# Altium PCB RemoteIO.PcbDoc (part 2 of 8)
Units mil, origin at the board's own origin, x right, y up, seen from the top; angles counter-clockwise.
Board outline 7874.02 x 2362.2 mil, 6 copper layers (Top Layer, GND1, Layer 2, PWR, GND2, Bottom Layer), stack 60.956 mil thick; 655 components, 447 nets, 2607 pads, 1444 vias.
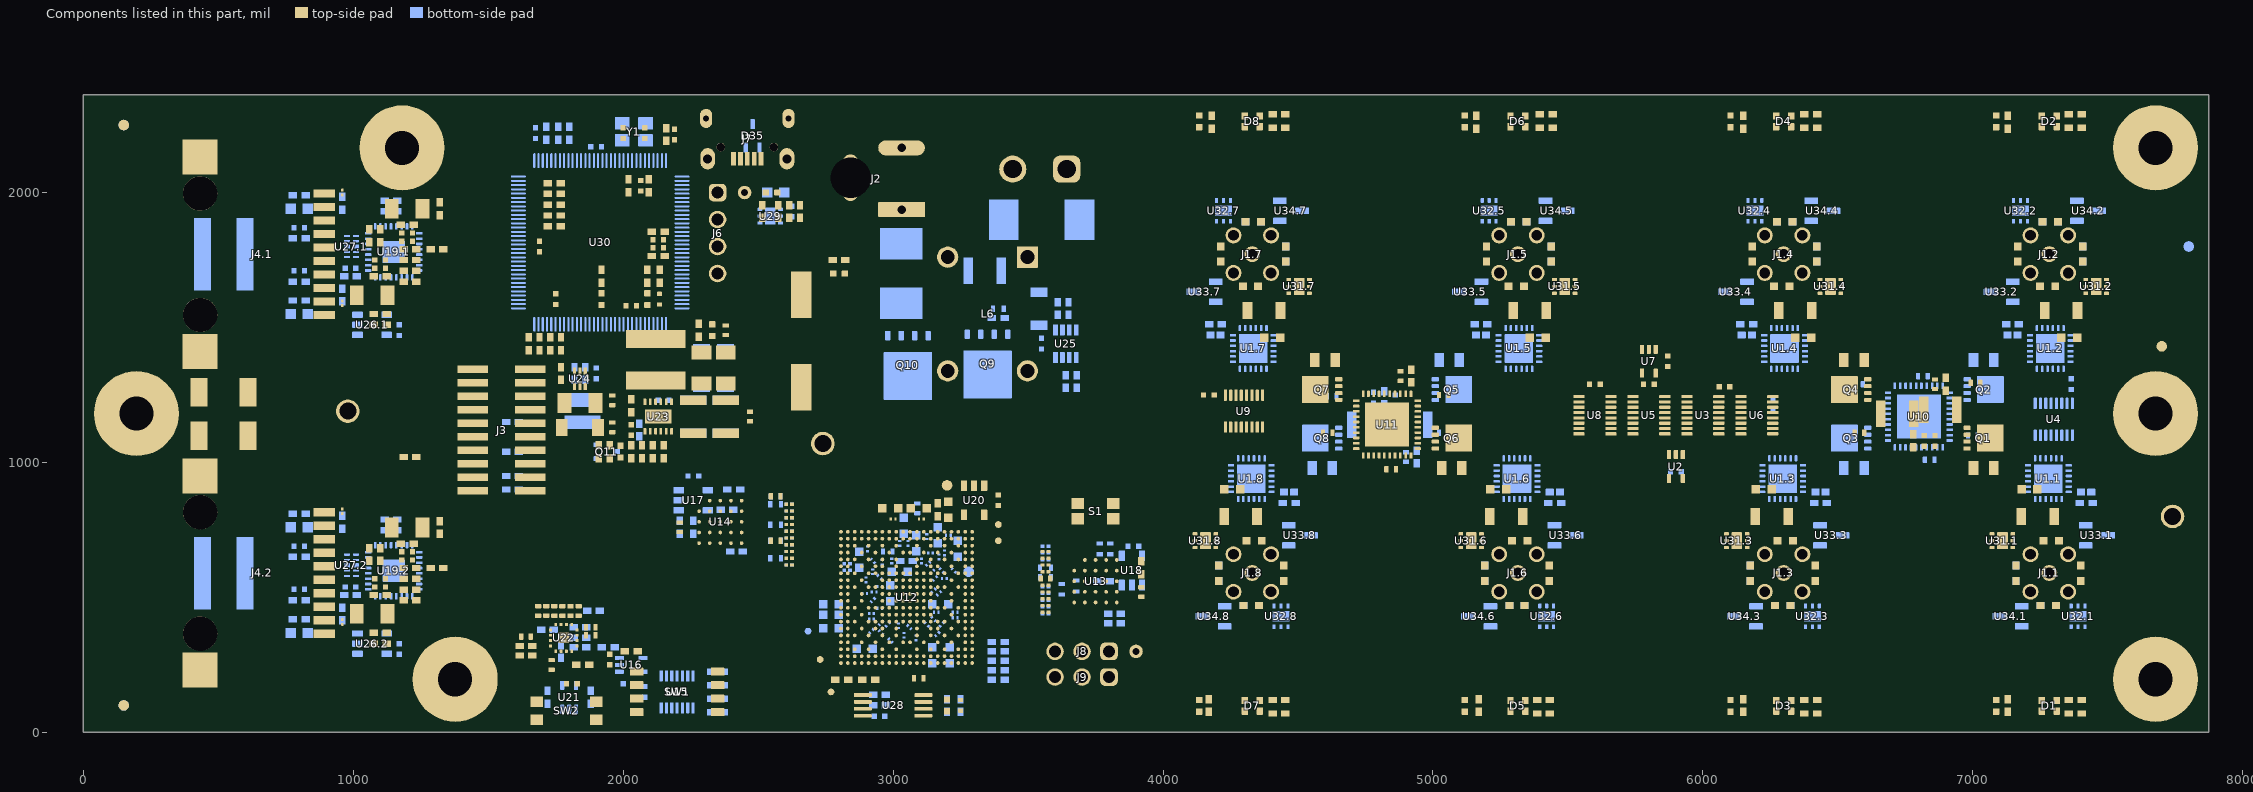
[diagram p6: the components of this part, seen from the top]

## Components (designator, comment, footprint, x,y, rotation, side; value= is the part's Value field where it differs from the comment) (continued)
R74 "RC0201JR-7D22RL" 0201L 2615,645 r180 top value=22
R75 "RC0201JR-7D22RL" 0201L 2615,695 r180 top value=22
R76 "RC0201JR-7D22RL" 0201L 2615,845 r180 top value=22
R77 "RC0201JR-7D22RL" 0201L 2615,820 r180 top value=22
R78 "RC0201JR-7D22RL" 0201L 2615,795 r180 top value=22
R79 "RC0201JR-7D22RL" 0201L 2615,745 r180 top value=22
R80 "RC0201JR-7D22RL" 0201L 2615,670 r180 top value=22
R81 "RC0201JR-7D22RL" 0201L 2615,620 r180 top value=22
R82 "RC0201JR-7D22RL" 0201L 2615,720 r180 top value=22
R83 "CRCW04021K00FKED" 0402S 2565,645 r0 bottom value=1.00k
R84 "RC0402FR-07100KL" 0402S 2565,770 r0 bottom value=100k
R85 "CRCW04020000Z0EDC" FP-CRCW04020000Z0EDC_0402-MFG 3565,570 r180 top value=0
R86 "CRCW02010000Z0ED" 0201L 2615,770 r0 top value=0
R87 "CRCW04020000Z0EDC" FP-CRCW04020000Z0EDC_0402-MFG 2565,875 r180 top value=0
R88 "CRCW04020000Z0EDC" FP-CRCW04020000Z0EDC_0402-MFG 2565,875 r180 bottom value=0
R89 "CRCW040210K0JNED" 0402 2350,75 r0 bottom value=10k
R90 "CRCW040210K0JNED" 0402 2350,125 r0 bottom value=10k
R91 "CRCW040210K0JNED" 0402 2350,175 r0 bottom value=10k
R92 "CRCW040210K0JNED" 0402 2350,225 r0 bottom value=10k
R93 "CRCW040268R0JNED" 0402 2030,300 r180 top value=68
R94 "CRCW040210K0JNED" 0402 2410,900 r0 bottom value=10k
R95 "CRCW040210K0JNED" 0402 2210,760 r270 bottom value=10k
R96 "CRCW040210K0JNED" 0402S 3765,680 r90 bottom value=10k
R97 "CRCW040210K0JNED" 0402 3920,610 r90 top value=10k
R98 "CRCW04020000Z0EDC" FP-CRCW04020000Z0EDC_0402-MFG 3920,520 r270 top value=0
R99 "CRCW04020000Z0EDC" FP-CRCW04020000Z0EDC_0402-MFG 2210,760 r270 top value=0
R100 "CRCW040210K0JNED" 0402 1880,130 r90 bottom value=10k
R101 "CRCW04020000Z0EDC" FP-CRCW04020000Z0EDC_0402-MFG 1880,360 r0 top value=0
R102 "CRCW04020000Z0EDC" FP-CRCW04020000Z0EDC_0402-MFG 1805,450 r90 top value=0
R103 "CRCW04020000Z0EDC" FP-CRCW04020000Z0EDC_0402-MFG 1715,450 r90 top value=0
R104 "CRCW04020000Z0EDC" FP-CRCW04020000Z0EDC_0402-MFG 1775,450 r90 top value=0
R105 "CRCW04020000Z0EDC" FP-CRCW04020000Z0EDC_0402-MFG 1880,390 r180 top value=0
R106 "CRCW04020000Z0EDC" FP-CRCW04020000Z0EDC_0402-MFG 1835,450 r270 top value=0
R107 "CRCW04020000Z0EDC" FP-CRCW04020000Z0EDC_0402-MFG 1685,450 r270 top value=0
R108 "CRCW04020000Z0EDC" FP-CRCW04020000Z0EDC_0402-MFG 1745,450 r270 top value=0
R109 "CRCW04020000Z0EDC" FP-CRCW04020000Z0EDC_0402-MFG 3090,830 r90 bottom value=0
R110 "CRCW04020000Z0EDC" FP-CRCW04020000Z0EDC_0402-MFG 2980,670 r0 bottom value=0
R111 "CRCW04020000Z0EDC" FP-CRCW04020000Z0EDC_0402-MFG 1735,250 r90 top value=0
R112 "CRCW04020000Z0EDC" FP-CRCW04020000Z0EDC_0402-MFG 1640,355 r0 top value=0
R113 "CRCW040210K0JNED" 0402 3820,405 r0 bottom value=10k
R114 "CRCW02010000Z0ED" 0201L 2830,625 r0 bottom value=0
R115 "CRCW02010000Z0ED" 0201L 2830,600 r0 bottom value=0
R117 "CRCW04020000Z0EDC" FP-CRCW04020000Z0EDC_0402-MFG 2380,1490 r90 top value=0
R118 "CRCW040233R0JNED" 0402 1640,285 r180 top value=33
R119 "CRCW040233R0JNED" 0402 1640,320 r180 top value=33
R120 "CRCW040233R0JNED" 0402 1850,250 r0 top value=33
R121 "RC0402FR-07100KL" 0402 2030,1210 r270 top value=100k
R122 "RC0402FR-07100KL" 0402 2070,1040 r270 top value=100k
R123 "CRCW04021K00FKED" 0402 2030,1040 r270 top value=1.00k
R124 "CRCW040231K6FKED" 0402 2060,1120 r270 bottom value=31.6k
R125 "CRCW04020000Z0EDC" FP-CRCW04020000Z0EDC_0402-MFG 1960,1130 r270 top value=0
R126 "CRCW0402107KFKED" 0402 1860,1330 r270 bottom value=107k
R127 "RC0402FR-07100KL" 0402 1770,1330 r270 top value=100k
R128 "RC0402FR-07100KL" 0402 1820,1330 r90 bottom value=100k
R129 "RC0402FR-07100KL" 0402 3610,1570 r270 bottom value=100k
R130 "RC0402FR-07100KL" 0402 3680,1300 r270 bottom value=100k
R131 "RC0402FR-07100KL" 0402 3390,1535 r0 bottom value=100k
R132 "CRCW04023K92FKED" 0402 3650,1570 r270 bottom value=3.92k
R133 "CRCW04027K50FKED" 0402 3640,1300 r90 bottom value=7.50k
R134 "RC0402FR-07100KL" 0402 2150,1040 r270 top value=100k
R135 "CRCW04028K87FKED" 0402 2110,1040 r90 top value=8.87k
R136 "CRCW040268K0JNED" 0402 2800,1750 r0 top value=68k
R137 "CRCW04020000Z0EDC" FP-CRCW04020000Z0EDC_0402-MFG 2470,1170 r90 top value=0
R138 "CRCW04023K30JNED" 0402 2280,1490 r270 top value=3.3k
R139 "CRCW04020000Z0EDC" FP-CRCW04020000Z0EDC_0402-MFG 1960,1230 r90 top value=0
R140 "CRCW04023K30JNED" 0402 1950,1040 r270 top value=3.3k
R141 "CRCW040210K0JNED" 0402 1910,1040 r90 top value=10k
R142 "CRCW04023K30JNED" 0402 3200,100 r90 bottom value=3.3k
R143 "CRCW04021K00FKED" 0402 3250,100 r90 bottom value=1.00k
R144 "CRCW040210K0JNED" 0402 3390,335 r180 bottom value=10k
R145 "CRCW040210K0JNED" 0402 2950,140 r180 bottom value=10k
R146 "CRCW040210K0JNED" 0402 2950,100 r180 bottom value=10k
R147 "CRCW040210K0JNED" 0402 1590,1150 r180 bottom value=10k
R148 "CRCW040210K0JNED" 0402 1590,950 r180 bottom value=10k
R149 "CRCW040210K0JNED" 0402 1590,1040 r180 bottom value=10k
R150 "CRCW040210K0JNED" 0402 1590,900 r180 bottom value=10k
R151 "CRCW040222R0JNED" 0402 3390,300 r180 bottom value=22
R152 "CRCW040222R0JNED" 0402 3390,195 r180 bottom value=22
R153 "CRCW040222R0JNED" 0402 3390,265 r180 bottom value=22
R154 "CRCW040222R0JNED" 0402 3390,230 r180 bottom value=22
R155 "CRCW04020000Z0EDC" FP-CRCW04020000Z0EDC_0402-MFG 7000,1100 r0 bottom value=0
R156 "CRCW04020000Z0EDC" FP-CRCW04020000Z0EDC_0402-MFG 7010,1295 r0 top value=0
R157 "CRCW04020000Z0EDC" FP-CRCW04020000Z0EDC_0402-MFG 6580,1110 r180 top value=0
R158 "CRCW04020000Z0EDC" FP-CRCW04020000Z0EDC_0402-MFG 6575,1290 r180 bottom value=0
R159 "CRCW04020000Z0EDC" FP-CRCW04020000Z0EDC_0402-MFG 5040,1250 r0 top value=0
R160 "CRCW04020000Z0EDC" FP-CRCW04020000Z0EDC_0402-MFG 5040,1110 r0 bottom value=0
R161 "CRCW04020000Z0EDC" FP-CRCW04020000Z0EDC_0402-MFG 4625,1245 r180 bottom value=0
R162 "CRCW04020000Z0EDC" FP-CRCW04020000Z0EDC_0402-MFG 4610,1110 r180 top value=0
R163.1 "CRCW04026K49FKED" 0402 1100,1840 r90 top value=6.49k (schematic designator R163)
R163.2 "CRCW04026K49FKED" 0402 1100,658.9 r90 top value=6.49k (schematic designator R163)
R164.1 "CRCW040210K0JNED" 0402 1100,1510 r0 top value=10k (schematic designator R164)
R164.2 "CRCW040210K0JNED" 0402 1100,328.9 r0 top value=10k (schematic designator R164)
R166.1 "CRCW04022K49FKED" 0402 960,1620 r90 bottom value=2.49k (schematic designator R166)
R166.2 "CRCW04022K49FKED" 0402 960,438.9 r90 bottom value=2.49k (schematic designator R166)
R167.1 "CRCW04022K49FKED" 0402 960,1960 r270 bottom value=2.49k (schematic designator R167)
R167.2 "CRCW04022K49FKED" 0402 960,778.9 r270 bottom value=2.49k (schematic designator R167)
R168.1 "CRCW04022K49FKED" 0402 1210,1710 r0 top value=2.49k (schematic designator R168)
R168.2 "CRCW04022K49FKED" 0402 1210,528.9 r0 top value=2.49k (schematic designator R168)
R171.1 "CRCW04022K49FKED" 0402 1310,1790 r0 top value=2.49k (schematic designator R171)
R171.2 "CRCW04022K49FKED" 0402 1310,608.9 r0 top value=2.49k (schematic designator R171)
R172.1 "CRCW04022K49FKED" 0402 1140,1970 r180 bottom value=2.49k (schematic designator R172)
R172.2 "CRCW04022K49FKED" 0402 1140,788.9 r180 bottom value=2.49k (schematic designator R172)
R176.1 "CRCW04021K50FKED" 0402 800,1600 r0 bottom value=1.50k (schematic designator R176)
R176.2 "CRCW04021K50FKED" 0402 800,418.9 r0 bottom value=1.50k (schematic designator R176)
R177.1 "CRCW04021K50FKED" 0402 800,1990 r0 bottom value=1.50k (schematic designator R177)
R177.2 "CRCW04021K50FKED" 0402 800,810 r0 bottom value=1.50k (schematic designator R177)
R178.1 "CRCW04021K50FKED" 0402 1210,1670 r180 top value=1.50k (schematic designator R178)
R178.2 "CRCW04021K50FKED" 0402 1210,488.9 r180 top value=1.50k (schematic designator R178)
R181.1 "CRCW04021K50FKED" 0402 1210,1790 r0 top value=1.50k (schematic designator R181)
R181.2 "CRCW04021K50FKED" 0402 1210,608.9 r0 top value=1.50k (schematic designator R181)
R182.1 "CRCW04021K50FKED" 0402 1140,1930 r0 bottom value=1.50k (schematic designator R182)
R182.2 "CRCW04021K50FKED" 0402 1140,748.9 r0 bottom value=1.50k (schematic designator R182)
R189.1 "CRCW040210K0JNED" 0402 990,1690 r180 bottom value=10k (schematic designator R189)
R189.2 "CRCW040210K0JNED" 0402 990,508.9 r180 bottom value=10k (schematic designator R189)
R190.1 "CRCW040210K0JNED" 0402 1210,1750 r180 top value=10k (schematic designator R190)
R190.2 "CRCW040210K0JNED" 0402 1210,568.9 r180 top value=10k (schematic designator R190)
R191.1 "CRCW0603220RJNEA" 0603 800,1550 r0 bottom value=220 (schematic designator R191)
R191.2 "CRCW0603220RJNEA" 0603 800,368.9 r0 bottom value=220 (schematic designator R191)
R192.1 "CRCW0603220RJNEA" 0603 800,1940 r0 bottom value=220 (schematic designator R192)
R192.2 "CRCW0603220RJNEA" 0603 800,760 r0 bottom value=220 (schematic designator R192)
R193.1 "CRCW20101M00JNEF" 2010 520,1259.84 r0 top value=1.0Meg (schematic designator R193)
R193.2 "CRCW20101M00JNEF" 2010 520,1098.9 r0 top value=1.0Meg (schematic designator R193)
R194 "CRCW040252K3FKED" 0402 2615,1930 r90 top value=52.3k
R195 "CRCW04023K30JNED" 0402 1920,1690 r270 top value=3.3k
R196 "CRCW040230K0FKED" 0402 2655,1930 r270 top value=30.0k
R197 "CRCW04021K00FKED" 0402 1745,2035 r0 top value=1.00k
R198 "CRCW04021K00FKED" 0402 1745,1995 r0 top value=1.00k
R199 "CRCW04021K00FKED" 0402 1745,1955 r0 top value=1.00k
R200 "CRCW04021K00FKED" 0402 1745,1915 r0 top value=1.00k
R201 "CRCW0402100RJNED" 0402 2160,2215 r270 top value=100
R203 "CRCW040222R0JNED" 0402 1650,1440 r90 top value=22
R204 "CRCW040222R0JNED" 0402 1690,1440 r90 top value=22
R205 "CRCW040222R0JNED" 0402 1730,1440 r90 top value=22
R206 "CRCW04021K00FKED" 0402 2135,1690 r270 top value=1.00k
R207 "CRCW04023K30JNED" 0402 2090,1690 r270 top value=3.3k
R208 "CRCW040210K0JNED" 0402 1760,2220 r270 bottom value=10k
R209 "CRCW040210K0JNED" 0402 1800,2220 r90 bottom value=10k
R210 "CRCW04024K87FKED" 0402 1745,1875 r180 top value=4.87k
R211 "CRCW040251R0JNED" 0402 1715,2220 r270 bottom value=51
R212 "CRCW040222R0JNED" 0402 1770,1440 r90 top value=22
R213 "CRCW06038K20JNEA" 0603 2565,2000 r0 bottom value=8.2k
RV1.1 "30VAC, 38VDC" WE-VS_0603 7290,710 r180 top value=30V (schematic designator RV1)
RV1.2 "30VAC, 38VDC" WE-VS_0603 7276.93,1652.2 r0 top value=30V (schematic designator RV1)
RV1.3 "30VAC, 38VDC" WE-VS_0603 6305.75,710 r180 top value=30V (schematic designator RV1)
RV1.4 "30VAC, 38VDC" WE-VS_0603 6292.68,1652.2 r0 top value=30V (schematic designator RV1)
RV1.5 "30VAC, 38VDC" WE-VS_0603 5308.43,1652.2 r0 top value=30V (schematic designator RV1)
RV1.6 "30VAC, 38VDC" WE-VS_0603 5321.5,710 r180 top value=30V (schematic designator RV1)
RV1.7 "30VAC, 38VDC" WE-VS_0603 4324.17,1652.2 r0 top value=30V (schematic designator RV1)
RV1.8 "30VAC, 38VDC" WE-VS_0603 4337.24,710 r180 top value=30V (schematic designator RV1)
RV2.1 "30VAC, 38VDC" WE-VS_0603 7160,590 r90 top value=30V (schematic designator RV2)
RV2.2 "30VAC, 38VDC" WE-VS_0603 7406.93,1772.2 r270 top value=30V (schematic designator RV2)
RV2.3 "30VAC, 38VDC" WE-VS_0603 6175.75,590 r90 top value=30V (schematic designator RV2)
RV2.4 "30VAC, 38VDC" WE-VS_0603 6422.68,1772.2 r270 top value=30V (schematic designator RV2)
RV2.5 "30VAC, 38VDC" WE-VS_0603 5438.43,1772.2 r270 top value=30V (schematic designator RV2)
RV2.6 "30VAC, 38VDC" WE-VS_0603 5191.5,590 r90 top value=30V (schematic designator RV2)
RV2.7 "30VAC, 38VDC" WE-VS_0603 4454.17,1772.2 r270 top value=30V (schematic designator RV2)
RV2.8 "30VAC, 38VDC" WE-VS_0603 4207.24,590 r90 top value=30V (schematic designator RV2)
RV3.1 "30VAC, 38VDC" WE-VS_0603 7160,590 r90 bottom value=30V (schematic designator RV3)
RV3.2 "30VAC, 38VDC" WE-VS_0603 7406.93,1772.2 r270 bottom value=30V (schematic designator RV3)
RV3.3 "30VAC, 38VDC" WE-VS_0603 6175.75,590 r90 bottom value=30V (schematic designator RV3)
RV3.4 "30VAC, 38VDC" WE-VS_0603 6422.68,1772.2 r270 bottom value=30V (schematic designator RV3)
RV3.5 "30VAC, 38VDC" WE-VS_0603 5438.43,1772.2 r270 bottom value=30V (schematic designator RV3)
RV3.6 "30VAC, 38VDC" WE-VS_0603 5191.5,590 r90 bottom value=30V (schematic designator RV3)
RV3.7 "30VAC, 38VDC" WE-VS_0603 4454.17,1772.2 r270 bottom value=30V (schematic designator RV3)
RV3.8 "30VAC, 38VDC" WE-VS_0603 4207.24,590 r90 bottom value=30V (schematic designator RV3)
RV4.1 "30VAC, 38VDC" WE-VS_0603 7400,590 r90 top value=30V (schematic designator RV4)
RV4.2 "30VAC, 38VDC" WE-VS_0603 7166.93,1772.2 r270 top value=30V (schematic designator RV4)
RV4.3 "30VAC, 38VDC" WE-VS_0603 6415.75,590 r90 top value=30V (schematic designator RV4)
RV4.4 "30VAC, 38VDC" WE-VS_0603 6182.68,1772.2 r270 top value=30V (schematic designator RV4)
RV4.5 "30VAC, 38VDC" WE-VS_0603 5198.43,1772.2 r270 top value=30V (schematic designator RV4)
RV4.6 "30VAC, 38VDC" WE-VS_0603 5431.5,590 r90 top value=30V (schematic designator RV4)
RV4.7 "30VAC, 38VDC" WE-VS_0603 4214.17,1772.2 r270 top value=30V (schematic designator RV4)
RV4.8 "30VAC, 38VDC" WE-VS_0603 4447.24,590 r90 top value=30V (schematic designator RV4)
RV5.1 "30VAC, 38VDC" WE-VS_0603 7280,470 r0 bottom value=30V (schematic designator RV5)
RV5.2 "30VAC, 38VDC" WE-VS_0603 7286.93,1892.2 r180 bottom value=30V (schematic designator RV5)
RV5.3 "30VAC, 38VDC" WE-VS_0603 6295.75,470 r0 bottom value=30V (schematic designator RV5)
RV5.4 "30VAC, 38VDC" WE-VS_0603 6302.68,1892.2 r180 bottom value=30V (schematic designator RV5)
RV5.5 "30VAC, 38VDC" WE-VS_0603 5318.43,1892.2 r180 bottom value=30V (schematic designator RV5)
RV5.6 "30VAC, 38VDC" WE-VS_0603 5311.5,470 r0 bottom value=30V (schematic designator RV5)
RV5.7 "30VAC, 38VDC" WE-VS_0603 4334.17,1892.2 r180 bottom value=30V (schematic designator RV5)
RV5.8 "30VAC, 38VDC" WE-VS_0603 4327.24,470 r0 bottom value=30V (schematic designator RV5)
RV6.1 "30VAC, 38VDC" WE-VS_0603 7280,470 r0 top value=30V (schematic designator RV6)
RV6.2 "30VAC, 38VDC" WE-VS_0603 7286.93,1892.2 r180 top value=30V (schematic designator RV6)
RV6.3 "30VAC, 38VDC" WE-VS_0603 6295.75,470 r0 top value=30V (schematic designator RV6)
RV6.4 "30VAC, 38VDC" WE-VS_0603 6302.68,1892.2 r180 top value=30V (schematic designator RV6)
RV6.5 "30VAC, 38VDC" WE-VS_0603 5318.43,1892.2 r180 top value=30V (schematic designator RV6)
RV6.6 "30VAC, 38VDC" WE-VS_0603 5311.5,470 r0 top value=30V (schematic designator RV6)
RV6.7 "30VAC, 38VDC" WE-VS_0603 4334.17,1892.2 r180 top value=30V (schematic designator RV6)
RV6.8 "30VAC, 38VDC" WE-VS_0603 4327.24,470 r0 top value=30V (schematic designator RV6)
S1 "434153017835" SW_434153017835 3750,820 r0 top
SW1 "416131160804" FP-416131160804_SMT_SW-MFG 2200,150 r270 top
SW2 "434351045816" FP-434351045816_SMT_SW_4MM7_4MM5-MFG 1790,80 r0 top
TP1 "TP_SM_1MM" TP_SM_1MM 3200,915 r0 top
TP2 "TP_SM_1MM" TP_SM_1MM 3280,595 r180 bottom
TP3 "5006" Keystone5006 7740,800 r0 top
TP4 "5006" Keystone5006 980,1190 r0 top
TP5 "5006" Keystone5006 2740,1070 r180 bottom
TP6 "TESTPOINT" TP_25MIL-SMT 3390,710 r90 top
TP7 "TESTPOINT" TP_25MIL-SMT 3390,770 r90 top
TP8 "TESTPOINT" TP_25MIL-SMT 2685,375 r90 bottom
TP9 "TESTPOINT" TP_50MIL-25MILHOLE 2450,2000 r90 top
TP10 "TESTPOINT" TP_25MIL-SMT 2730,270 r90 top
TP11 "TESTPOINT" TP_25MIL-SMT 2770,150 r90 top
TP12 "TESTPOINT" TP_50MIL-25MILHOLE 3900,300 r90 top
U1.1 "TIOL221RGE" RGE0024H-MFG 7280,940 r180 bottom (schematic designator U1)
U1.2 "TIOL221RGE" RGE0024H-MFG 7286.93,1422.2 r0 bottom (schematic designator U1)
U1.3 "TIOL221RGE" RGE0024H-MFG 6295.75,940 r180 bottom (schematic designator U1)
U1.4 "TIOL221RGE" RGE0024H-MFG 6302.68,1422.2 r0 bottom (schematic designator U1)
U1.5 "TIOL221RGE" RGE0024H-MFG 5318.43,1422.2 r0 bottom (schematic designator U1)
U1.6 "TIOL221RGE" RGE0024H-MFG 5311.5,940 r180 bottom (schematic designator U1)
U1.7 "TIOL221RGE" RGE0024H-MFG 4334.17,1422.2 r0 bottom (schematic designator U1)
U1.8 "TIOL221RGE" RGE0024H-MFG 4327.24,940 r180 bottom (schematic designator U1)
U2 "SN74LVC1G125DCKR" DCK0005A_N 5900,985 r270 top
U3 "SN74HCS594DYYR" DYY0016A-MFG 6000,1175 r0 top
U4 "SN74HCS594DYYR" DYY0016A-MFG 7300,1160 r90 bottom
U5 "SN74HCS165DYYR" DYY0016A-MFG 5800,1175 r0 top
U6 "SN74HCS594DYYR" DYY0016A-MFG 6200,1175 r0 top
U7 "SN74LVC1G14DCKR" DCK0005A_N 5800,1375 r270 top
U8 "SN74HCS594DYYR" DYY0016A-MFG 5600,1175 r0 top
U9 "SN74HCS594DYYR" DYY0016A-MFG 4300,1190 r90 top
U10 "TPS274C65AS" RHA0040M-MFG 6800,1170 r90 bottom
U11 "TPS274C65AS" RHA0040M-MFG 4830,1140 r270 top
U12 "AM2612AOFFHIZFGR" ZFG0304A-MFG 3050,500 r180 top locked
U13 "MX25LM51245GXDI00" MXIC_BGA24-6x8MM 3750,560 r0 top
U14 "APS12808L-3OBM-BA" FP-APS12808L-3OBM-BA_BGA24-IPC_C 2360,780 r0 top
U15 "SN74HCS125DYYR" DYY0014A-MFG 2200,150 r270 bottom
U16 "SN74LVC1G17DCKR" DCK0005A_N 2030,250 r0 bottom
U17 "SN74AHC1G09DBVR" DBV0005A_N 2260,860 r0 bottom
U18 "SN74AHC1G09DBVR" DBV0005A_N 3885,600 r90 bottom
U19.1 "DP83826A" RHB0032M-MFG 1150,1780 r0 bottom (schematic designator U19)
U19.2 "DP83826A" RHB0032M-MFG 1150,598.9 r0 bottom (schematic designator U19)
U20 "SN74LVC1G08DBVR" DBV0005A_N 3300,860 r270 top
U21 "SN74LVC1G17DCKR" DCK0005A_N 1800,130 r90 bottom
U22 "LMK3C0105V33RERR" RER0016A-MFG 1780,350 r270 top
U23 "LMR51425FNDRRR" DRR0012E-MFG 2130,1170 r270 top
U24 "TPS62A03ADRLR" DRL0006A-MFG 1840,1310 r90 top
U25 "LM74502DDF" DDF0008A-MFG 3640,1440 r90 bottom
U26.1 "SN74AHC1G09DBVR" DBV0005A_N 1070,1510 r0 bottom (schematic designator U26)
U26.2 "SN74AHC1G09DBVR" DBV0005A_N 1070,328.9 r0 bottom (schematic designator U26)
U27.1 "ESD204DQAR" DQA0010A 993.56,1800 r0 bottom (schematic designator U27)
U27.2 "ESD204DQAR" DQA0010A 993.56,618.9 r0 bottom (schematic designator U27)
U28 "24AA256-I/ST" TSSOP-8 3000,100 r180 top
U29 "TPS7A3701DRVR" DRV0006A#1 2545,1912.28 r180 bottom
U30 "MSP432E401YTPDT" PDT0128A 1915,1815 r90 bottom
U31.1 "TVS3300DRVR" DRV0006A#2 7110,710 r180 top (schematic designator U31)
U31.2 "TVS3300DRVR" DRV0006A#2 7456.93,1652.2 r0 top (schematic designator U31)
U31.3 "TVS3300DRVR" DRV0006A#2 6125.75,710 r180 top (schematic designator U31)
U31.4 "TVS3300DRVR" DRV0006A#2 6472.68,1652.2 r0 top (schematic designator U31)
U31.5 "TVS3300DRVR" DRV0006A#2 5488.43,1652.2 r0 top (schematic designator U31)
U31.6 "TVS3300DRVR" DRV0006A#2 5141.5,710 r180 top (schematic designator U31)
U31.7 "TVS3300DRVR" DRV0006A#2 4504.17,1652.2 r0 top (schematic designator U31)
U31.8 "TVS3300DRVR" DRV0006A#2 4157.24,710 r180 top (schematic designator U31)
U32.1 "TVS3300DRVR" DRV0006A#1 7390,430 r270 bottom (schematic designator U32)
U32.2 "TVS3300DRVR" DRV0006A#1 7176.93,1932.2 r90 bottom (schematic designator U32)
U32.3 "TVS3300DRVR" DRV0006A#1 6405.75,430 r270 bottom (schematic designator U32)
U32.4 "TVS3300DRVR" DRV0006A#1 6192.68,1932.2 r90 bottom (schematic designator U32)
U32.5 "TVS3300DRVR" DRV0006A#1 5208.43,1932.2 r90 bottom (schematic designator U32)
U32.6 "TVS3300DRVR" DRV0006A#1 5421.5,430 r270 bottom (schematic designator U32)
U32.7 "TVS3300DRVR" DRV0006A#1 4224.17,1932.2 r90 bottom (schematic designator U32)
U32.8 "TVS3300DRVR" DRV0006A#1 4437.24,430 r270 bottom (schematic designator U32)
U33.1 "TSM36ADBZR" DBZ0003A-MFG 7460,730 r0 bottom (schematic designator U33)
U33.2 "TSM36ADBZR" DBZ0003A-MFG 7106.93,1632.2 r180 bottom (schematic designator U33)
U33.3 "TSM36ADBZR" DBZ0003A-MFG 6475.75,730 r0 bottom (schematic designator U33)
U33.4 "TSM36ADBZR" DBZ0003A-MFG 6122.68,1632.2 r180 bottom (schematic designator U33)
U33.5 "TSM36ADBZR" DBZ0003A-MFG 5138.43,1632.2 r180 bottom (schematic designator U33)
U33.6 "TSM36ADBZR" DBZ0003A-MFG 5491.5,730 r0 bottom (schematic designator U33)
U33.7 "TSM36ADBZR" DBZ0003A-MFG 4154.17,1632.2 r180 bottom (schematic designator U33)
U33.8 "TSM36ADBZR" DBZ0003A-MFG 4507.24,730 r0 bottom (schematic designator U33)
U34.1 "TSM36ADBZR" DBZ0003A-MFG 7140,430 r180 bottom (schematic designator U34)
U34.2 "TSM36ADBZR" DBZ0003A-MFG 7426.93,1932.2 r0 bottom (schematic designator U34)
U34.3 "TSM36ADBZR" DBZ0003A-MFG 6155.75,430 r180 bottom (schematic designator U34)
U34.4 "TSM36ADBZR" DBZ0003A-MFG 6442.68,1932.2 r0 bottom (schematic designator U34)
U34.5 "TSM36ADBZR" DBZ0003A-MFG 5458.43,1932.2 r0 bottom (schematic designator U34)
U34.6 "TSM36ADBZR" DBZ0003A-MFG 5171.5,430 r180 bottom (schematic designator U34)
U34.7 "TSM36ADBZR" DBZ0003A-MFG 4474.17,1932.2 r0 bottom (schematic designator U34)
U34.8 "TSM36ADBZR" DBZ0003A-MFG 4187.24,430 r180 bottom (schematic designator U34)
Y1 "830064296" FP-830064296_SMT4_3MM4_2MM7-MFG 2040,2225 r180 bottom
ZZ1 "This Assembly Note is for PCB labels only" AssemblyNoteLabel 118.11,3090.55 r0 top
ZZ2 "These assemblies are ESD sensitive, ESD precautions shall be observed." AssemblyNote 118.11,2992.13 r0 top
ZZ3 "These assemblies must be clean and free from flux and all contaminants. Use of no clean flux is not acceptable." AssemblyNote 118.11,2893.7 r0 top
ZZ4 "These assemblies must comply with workmanship standards IPC-A-610 Class 2, unless otherwise specified." AssemblyNote 118.11,2795.28 r0 top

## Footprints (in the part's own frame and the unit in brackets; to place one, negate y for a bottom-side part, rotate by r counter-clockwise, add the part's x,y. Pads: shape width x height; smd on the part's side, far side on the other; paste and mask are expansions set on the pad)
0201L [mm] "Data from Kemet datasheet CC101_COM dated 7/28/11"
  rect 0.36x0.32 smd mask+0.048: 1(-0.28,0) 2(0.28,0)
  body extent -0.31,-0.16 0.31,0.16, height 0.26
0402 [mm] "0402 from SM-752 data"
  rect 0.8x0.6 smd: 1(-0.6,0) 2(0.6,0)
  silkscreen extent -1.22,-0.52 1.22,0.52, body extent -0.55,-0.3 0.55,0.3, height 0.6
0402S [mil] "Based on C0402S footprint from PADS legacy"
  rect 15x24 smd: 1(-20,0) 2(20,0)
  body extent -22,-12 22,12, height 24
0603 [mm] "0603 from SM-752 data"
  rect 1x0.95 smd: 1(-0.8,0) 2(0.8,0)
  silkscreen extent -1.52,-0.69 1.52,0.69, body extent -0.87,-0.47 0.87,0.47, height 1
1206 [mm] "1206 from SM-752 data"
  rect 1.3x1.85 smd: 1(-1.45,0) 2(1.45,0)
  silkscreen extent -2.4,-1.21 2.4,1.21, body extent -1.7,-0.9 1.7,0.9, height 1.35
1206_190 [mm] "1206_190"
  rect 1.1x1.6 smd: 1(-1.7,0) 2(1.7,0)
  silkscreen extent -0.9,-1 0.9,1, body extent -1.75,-0.95 1.75,0.95, height 1.9
1825 [mm] "Chip Capacitor, Body 4.5x6.4mm, IPC Medium Density"
  rect 1.6x6.8 smd: 1(-2,0) 2(2,0)
  silkscreen extent -3.11,-3.7 3.11,3.7, body extent -2.4,-3.4 2.4,3.4, height 1.1
2010 [mm] "Chip Capacitor, Body 5.08x2.54mm, IPC Medium Density"
  rect 1.6x2.7 smd: 1(-2.3,0) 2(2.3,0)
  silkscreen extent -3.42,-1.65 3.42,1.65, body extent -2.73,-1.45 2.73,1.45, height 1.66
7498011211 [mm] "Integrated RJ45 Transformer, THT, body 15.95 x 21.65 mm"
  rect 0.76x2.03 smd: 1(-5.715,11.68) 2(-4.445,11.68) 3(-3.175,11.68) 4(-1.905,11.68) 5(-0.635,11.68) 6(0.635,11.68) 7(1.905,11.68) 8(3.175,11.68) 9(4.445,11.68) 10(5.715,11.68)
  round 3.22 hole 3.22 unplated: MH1(-5.715,0) MH2(5.715,0)
  rect 3.3x3.3 smd: Shell(-9.145,0) Shell(9.145,0)
  silkscreen extent -8.91,-10.84 8.91,10.84, body extent -9.92,-10.81 9.92,11.91, height 14.45
643260100605 [mm] "FEMALE METAL STRAIGHT FRONT SIMPLE  PG9"
  round 1.5 hole 1: 1(-1.768,1.768) 2(1.768,1.768) 3(1.768,-1.768) 4(-1.768,-1.768) 5(0,0)
  silkscreen extent -9,-10 9,10.62, body extent -9.03,-10 9.04,10, height 23.05
691305540002 [mm] "5,08mm - PCB Header Horizontal Entry with Plastic Latches - 02p"
  rrect50% 2.55x2.55 hole 1.7: 1(-2.54,4)
  round 2.55 hole 1.7: 2(2.54,4)
  silkscreen extent -7.65,-6.15 7.65,6.15, body extent -7.48,-6 7.48,6, height 8.63
AssemblyNote [mil] "Assembly Note"
AssemblyNoteLabel [mil] "Assembly Note for PCB Labels"
CE_Mark_5mm [mil] "Minimum text height for CE Mark"
  silkscreen extent -138,-98 138,98
DBV0005A_N [mm] "SOT23, 5-Leads, Body 2.9x1.6mm, Pitch 0.95mm, Lead Span 2.8mm, IPC Medium Density"
  rrect17% 1x0.6 smd: 1(-1.375,0.95) 2(-1.375,0) 3(-1.375,-0.95) 4(1.375,-0.95) 5(1.375,0.95)
  silkscreen extent -1.63,-1.55 0.38,1.55, body extent -1.42,-1.46 1.42,1.46, height 1.09
DBZ0003A-MFG [mm]
  rrect17% 1.3x0.6 smd paste+0 mask+0: 1(-1.05,0.95) 2(-1.05,-0.95) 3(1.05,0)
  silkscreen extent -0.03,-1.52 0.7,1.52, body extent -1.18,-1.46 1.18,1.46, height 1.12
DCK0003A-MFG [mm]
  rrect25% 0.95x0.4 smd paste+0 mask+0: 1(-1.1,0.65) 2(-1.1,-0.65) 3(1.1,0)
  silkscreen extent -0.7,-1.07 0.7,1.07, body extent -1.06,-1 1.06,1, height 1.1
DCK0005A_N [mm] "SOT353, 5-Leads, Body 2x1.3mm, Pitch 0.65mm, Lead Span 2.1mm, IPC Medium Density"
  rrect25% 0.85x0.4 smd: 1(-1.125,0.65) 2(-1.125,0) 3(-1.125,-0.65) 4(1.125,-0.65) 5(1.125,0.65)
  silkscreen extent -1.48,-1.02 0.55,1.1, body extent -1.14,-1 1.14,1, height 0.95
DDF0008A-MFG [mm]
  rrect22% 1.05x0.45 smd paste+0 mask+0: 1(-1.3,0.975) 2(-1.3,0.325) 3(-1.3,-0.325) 4(-1.3,-0.975) 5(1.3,-0.975) 6(1.3,-0.325) 7(1.3,0.325) 8(1.3,0.975)
  silkscreen extent -2.5,-1.48 0.4,1.48, body extent -1.41,-1.45 1.41,1.45, height 1.1
DNH0008A#1 [mm] "VSONP-8"
  rrect50% 0.7x0.4 smd paste-0.05 mask-0.05: 1(-1.55,0.975) 2(-1.55,0.325) 3(-1.55,-0.325) 4(-1.55,-0.975) 5(1.55,-0.975) 6(1.55,-0.325) 7(1.55,0.325) 8(1.55,0.975)
  rrect4% 2.51x2.55 smd paste-1.5 mask-1.5: 9(0.645,0)
  rrect14% 0.705x1.125 on Top Paste: 9A(-0.208,0.662) 9B(0.697,0.662) 9C(-0.208,-0.663) 9D(0.697,-0.663)
  silkscreen extent -1.62,-1.7 1.62,1.7, body extent -1.65,-1.65 1.65,1.66, height 0.91
DNH0008A#2 [mm] "VSONP-8"
  rrect50% 0.7x0.4 smd paste-0.05 mask-0.05: 1(-1.55,0.975) 2(-1.55,0.325) 3(-1.55,-0.325) 4(-1.55,-0.975) 5(1.55,-0.975) 6(1.55,-0.325) 7(1.55,0.325) 8(1.55,0.975)
  rrect4% 2.51x2.55 smd paste-1.5 mask-1.5: 9(0.645,0)
  rrect14% 0.705x1.125 on Bottom Paste: 9A(-0.208,0.662) 9B(0.697,0.662) 9C(-0.208,-0.663) 9D(0.697,-0.663)
  silkscreen extent -1.62,-1.7 1.62,1.7, body extent -1.65,-1.66 1.65,1.66, height 0.91
DPL0002A-MFG [mm]
  rrect40% 0.28x0.25 smd paste+0 mask+0: 1(-0.22,0) 2(0.22,0)
  silkscreen extent -1.05,-0.5 0.4,0.5, body extent -0.46,-0.28 0.46,0.28, height 0.25
DQA0010A [mm] "SON, 10-Leads, Body 1x2.5mm, Pitch 0.5mm, TI Recommended"
  rrect50% 0.565x0.2 smd: 1(-0.417,1) 2(-0.417,0.5) 4(-0.417,-0.5) 5(-0.417,-1) 6(0.417,-1) 7(0.417,-0.5) 9(0.417,0.5) 10(0.417,1)
  rrect28% 0.565x0.36 on Bottom Paste: 3(-0.417,0) 8(0.417,0)
  rrect25% 0.565x0.4 smd paste-0.2: 3(-0.417,0) 8(0.417,0)
  silkscreen extent -0.67,-1.45 0.55,1.45, body extent -0.55,-1.3 0.55,1.3, height 0.56
DQJ0008A [mm] "SMD, 8-Leads, Body 5.75x4.9mm"
  rrect39% 0.91x0.51 smd paste-0.05 mask-0.05: 1(-2.795,1.905) 2(-2.795,0.635) 3(-2.795,-0.635) 4(-2.795,-1.905) 5(2.795,-1.905) 6(2.795,-0.635) 7(2.795,0.635) 8(2.795,1.905)
  rrect8% 1.58x1.25 on Bottom Paste: 9(-0.38,-1.45) 9(-0.38,0) 9(-0.38,1.45) 9(1.4,-1.45) 9(1.4,0) 9(1.4,1.45)
  rrect3% 3.48x4.47 on Bottom Solder: 9(0.55,0)
  rrect2% 4.49x4.57 smd paste-2.5 mask-2.5: 9(1.005,0)
  silkscreen extent -3,-2.6 3,2.6, body extent -3.13,-2.45 3.13,2.45, height 1.15
DRL0006A-MFG [mm]
  rrect33% 0.67x0.3 smd paste+0 mask+0: 1(-0.74,0.5) 2(-0.74,0) 3(-0.74,-0.5) 4(0.74,-0.5) 5(0.74,0) 6(0.74,0.5)
  silkscreen extent -1.75,-1.05 0.65,1.05, body extent -1.17,-1.1 1.17,1.1, height 0.25
DRR0012E-MFG [mm]
  rrect40% 0.62x0.25 smd paste+0 mask+0: 1(-1.39,1.25) 2(-1.39,0.75) 3(-1.39,0.25) 4(-1.39,-0.25) 5(-1.39,-0.75) 6(-1.39,-1.25) 7(1.39,-1.25) 8(1.39,-0.75) 9(1.39,-0.25) 10(1.39,0.25) 11(1.39,0.75) 12(1.39,1.25)
  rrect8% 1.3x2.5 smd paste-1000 mask+0: 13(0,0)
  silkscreen extent -2.37,-1.75 1.55,1.75, body extent -1.8,-1.65 1.8,1.65, height 0.25
DRV0006A#1 [mm] "SON, 6-Leads, Body 2x2mm, Pitch 0.65mm, Thermal Pad 1.6x1mm, TI Recommended"
  rrect33% 0.45x0.3 smd: 1(-0.975,0.65) 2(-0.975,0) 3(-0.975,-0.65) 4(0.975,-0.65) 5(0.975,0) 6(0.975,0.65)
  rrect14% 1x0.7 on Bottom Paste: 7(0,-0.45) 7(0,0.45)
  rrect10% 1x1.6 smd paste-0.5: 7(0,0)
  silkscreen extent -1.05,-1.2 1.05,1.2, body extent -1.05,-1.05 1.05,1.05, height 0.81
DRV0006A#2 [mm] "SON, 6-Leads, Body 2x2mm, Pitch 0.65mm, Thermal Pad 1.6x1mm, TI Recommended"
  rrect33% 0.45x0.3 smd: 1(-0.975,0.65) 2(-0.975,0) 3(-0.975,-0.65) 4(0.975,-0.65) 5(0.975,0) 6(0.975,0.65)
  rrect14% 1x0.7 on Top Paste: 7(0,0.45) 7(0,-0.45)
  rrect10% 1x1.6 smd paste-0.5: 7(0,0)
  silkscreen extent -1.05,-1.2 1.05,1.2, body extent -1.05,-1.05 1.05,1.05, height 0.81
DYY0014A-MFG [mm] "Recommended Land Pattern"
  rrect33% 1.05x0.3 smd paste+0 mask+0: 1(-1.5,1.5) 2(-1.5,1) 3(-1.5,0.5) 4(-1.5,0) 5(-1.5,-0.5) 6(-1.5,-1) 7(-1.5,-1.5) 8(1.5,-1.5) 9(1.5,-1) 10(1.5,-0.5) 11(1.5,0) 12(1.5,0.5) 13(1.5,1) 14(1.5,1.5)
  silkscreen extent -2.72,-2.15 1.05,2.15, body extent -1.63,-2.1 1.63,2.1, height 1.1
DYY0016A-MFG [mm]
  rrect33% 1.05x0.3 smd paste+0 mask+0: 1(-1.5,1.75) 2(-1.5,1.25) 3(-1.5,0.75) 4(-1.5,0.25) 5(-1.5,-0.25) 6(-1.5,-0.75) 7(-1.5,-1.25) 8(-1.5,-1.75) 9(1.5,-1.75) 10(1.5,-1.25) 11(1.5,-0.75) 12(1.5,-0.25) 13(1.5,0.25) 14(1.5,0.75) 15(1.5,1.25) 16(1.5,1.75)
  silkscreen extent -2.7,-2.15 0.55,2.15, body extent -2.12,-2.4 2.12,2.4, height 0.25
FCC_disclaimer [mil]
Fiducial10-20 [mm]
  round 1 smd mask+0.5: 1(0,0)
  Top Layer keep-out circle w1.178: c0,0 r0.5
FP-150040RS73220_0402-MFG [mm]
  rrect25% 0.4x0.46 smd paste+0 mask+0: 1(-0.5,0) 2(0.5,0)
  silkscreen extent -1.37,-0.61 0.5,0.61, body extent -0.8,-0.4 0.8,0.4, height 0.25
FP-150066RG74000_0606-MFG [mm] "Recommended Land Pattern"
  rrect17% 0.6x0.7 smd paste+0 mask+0: 1(-0.7,0.5) 2(-0.7,-0.5) 3(0.7,-0.5) 4(0.7,0.5)
  silkscreen extent -1.67,-0.85 0,0.85, body extent -0.8,-0.8 0.8,0.8, height 0.8
FP-830064296_SMT4_3MM4_2MM7-MFG [mm]
  rrect9% 1.4x1.15 smd paste+0 mask+0: 1(-1.1,-0.8) 2(1.1,-0.8) 3(1.1,0.8) 4(-1.1,0.8)
  silkscreen extent -2.17,-2.05 2.17,1.35, body extent -1.7,-1.35 1.7,1.35, height 0.8
FP-7448031002_PTH4_23MM0_17MM0-MFG [mm]
  rrect5% 2x2 hole 1.3 paste-2539.97 mask+0: 1(-3.75,-5.35)
  round 2 hole 1.3 paste-2539.97 mask+0: 2(3.75,-5.35) 3(3.75,5.35) 4(-3.75,5.35)
  silkscreen extent -11.5,-9.2 11.5,8.5, body extent -11.6,-8.6 11.6,8.6, height 0.25
FP-416131160804_SMT_SW-MFG [mm]
  rrect13% 0.76x1.27 smd paste+0 mask+0: 1(-1.905,-3.81) 2(-0.635,-3.81) 3(0.635,-3.81) 4(1.905,-3.81) 5(1.905,3.81) 6(0.635,3.81) 7(-0.635,3.81) 8(-1.905,3.81)
  silkscreen extent -3.27,-5.33 3.27,2.93, body extent -3.37,-4.54 3.37,4.54, height 0.25
FP-434351045816_SMT_SW_4MM7_4MM5-MFG [mm]
  rrect10% 1.2x1 smd paste+0 mask+0: 1(2.8,0.85) 2(2.8,-0.85) 3(-2.8,0.85) 4(-2.8,-0.85)
  silkscreen extent -2.4,0.73 4.08,1.85, body extent -3.5,-2.95 3.5,1.95, height 0.25
FP-629105150521_CONN_USB_8MM0_6MM6-MFG [mm]
  rect 0.45x1.3 smd: 1(-1.3,0) 2(-0.65,0) 3(0,0) 4(0.65,0) 5(1.3,0)
  oval 1.4x2 hole 0.85 slot 1.4 at 90 deg: Z1(-3.725,0) Z2(3.725,0)
  oval 1.15x1.8 hole 0.55 slot 1.2 at 90 deg: Z3(3.875,-3.8) Z4(-3.875,-3.8)
  round 0.8 hole 0.8 unplated: ""(-2.5,-1.1) ""(2.5,-1.1)
  silkscreen extent -4,-6.2 4,0.9, body extent -4,-6.25 4,0.35, height 2.67
FP-694106301002_CONN_PWR_JACK-MFG [mm] "Recommended Land Pattern"
  rrect7% 4.4x1.4 hole 0.8 slot 3.8 at 0 deg paste-2539.97 mask+0: 1(0,6.35)
  rrect100% 4.4x1.4 hole 0.8 slot 3.8 at 0 deg paste-2539.97 mask+0: 2(0,0.55)
  rrect100% 1.4x4.4 hole 3.8 slot 0.8 at 0 deg paste-2539.97 mask+0: 3(4.8,3.35)
  silkscreen extent -4.75,-7.4 4.75,7.4, body extent -4.5,-7.34 5,7.16, height 10.73
FP-885012005080_0402-MFG [mm]
  rrect20% 0.5x0.5 smd paste+0 mask+0: 1(-0.5,0) 2(0.5,0)
  silkscreen extent -0.53,-0.63 0.53,0.63, body extent -0.85,-0.38 0.85,0.38, height 0.25
FP-885012209048_1210-MFG [mm]
  rrect11% 0.9x2.5 smd paste+0 mask+0: 1(-1.55,0) 2(1.55,0)
  silkscreen extent -0.72,-1.35 0.72,1.35, body extent -1.6,-1.25 1.6,1.25, height 2.7
FP-885392005127_0402-MFG [mm] "Recommended Land Pattern"
  rrect20% 0.5x0.5 smd paste+0 mask+0: 1(-0.5,0) 2(0.5,0)
  silkscreen extent -0.5,-0.63 0.5,0.63, body extent -0.5,-0.25 0.5,0.25, height 0.55
FP-APS12808L-3OBM-BA_BGA24-IPC_C [mm]
  round 0.34 smd paste+0 mask+0: A2(-1,2) A3(0,2) A4(1,2) A5(2,2) B1(-2,1) B2(-1,1) B3(0,1) B4(1,1) B5(2,1) C1(-2,0) C2(-1,0) C3(0,0) C4(1,0) C5(2,0) D1(-2,-1) D2(-1,-1) D3(0,-1) D4(1,-1) D5(2,-1) E1(-2,-2) E2(-1,-2) E3(0,-2) E4(1,-2) E5(2,-2)
  silkscreen extent -3.6,-4 3,4, body extent -3,-4 3,4, height 1.2
FP-CRCW04020000Z0EDC_0402-IPC_A [mil]
  rrect15% 29.91x26.48 smd paste+0 mask+0: 1(-18.75,0) 2(18.75,0)
  silkscreen extent -34,-29 34,29, body extent -20,-10 20,10, height 14
FP-CRCW04020000Z0EDC_0402-MFG [mm]
  rrect25% 0.4x0.6 smd paste+0 mask+0: 1(-0.45,0) 2(0.45,0)
  silkscreen extent -0.55,-0.67 0.55,0.67, body extent -0.5,-0.25 0.5,0.25, height 0.35
FUSE_6125FF [mm] "SMT, 2-Leads, Body 6.1x2.72mm"
  rect 3x4 smd: 1(-2.8,0) 2(2.8,0)
  silkscreen extent -4.7,-2.4 4.7,2.4, body extent -3.15,-1.43 3.15,1.44, height 2.87
Keystone5006 [mil] "Keystone Compact loops"
  round 87 hole 63: 1(0,0)
  silkscreen extent -70,-70 70,70, body extent -63,-63 62,63, height 225
Keystone_1902C [mil] "Hex Standoff, 4-40 threaded, nylon"
  round 1 on Mech4: 0(0,0)
  body extent -145,-126 146,126, height 501
Label_650x200 [mil] "Thermal Transfer Label"
  round 1 on Mech14: 0(0,0)
  silkscreen extent -325,-100 325,100, body extent -325,-100 325,100, height 1
MXIC_BGA24-6x8MM [mm] "BGA, 24-Balls, Body 6x8mm, Pitch 1mm"
  round 0.35 smd: A2(-1,2) A3(0,2) A4(1,2) A5(2,2) B1(-2,1) B2(-1,1) B3(0,1) B4(1,1) B5(2,1) C1(-2,0) C2(-1,0) C3(0,0) C4(1,0) C5(2,0) D1(-2,-1) D2(-1,-1) D3(0,-1) D4(1,-1) D5(2,-1) E1(-2,-2) E2(-1,-2) E3(0,-2) E4(1,-2) E5(2,-2)
  body extent -3,-4 3,4, height 1.2
"NY PMS 440 0025 PH" [mm] "4-40 nylon screw and mounting hole"
  round 8 hole 3.2: 1(0,0)
  body extent -3.3,-3.3 3.3,3.3, height 2.69
PDT0128A [mm] "Thin QFP, 128-Leads, Body 14x14mm, Pitch 0.4mm"
  oval 1.4x0.2 smd: 1(-7.7,6.2) 2(-7.7,5.8) 3(-7.7,5.4) 4(-7.7,5) 5(-7.7,4.6) 6(-7.7,4.2) 7(-7.7,3.8) 8(-7.7,3.4) 9(-7.7,3) 10(-7.7,2.6) 11(-7.7,2.2) 12(-7.7,1.8) 13(-7.7,1.4) 14(-7.7,1) 15(-7.7,0.6) 16(-7.7,0.2) 17(-7.7,-0.2) 18(-7.7,-0.6) 19(-7.7,-1) 20(-7.7,-1.4) 21(-7.7,-1.8) 22(-7.7,-2.2) 23(-7.7,-2.6) 24(-7.7,-3) 25(-7.7,-3.4) 26(-7.7,-3.8) 27(-7.7,-4.2) 28(-7.7,-4.6) 29(-7.7,-5) 30(-7.7,-5.4) 31(-7.7,-5.8) 32(-7.7,-6.2) 65(7.7,-6.2) 66(7.7,-5.8) 67(7.7,-5.4) 68(7.7,-5) 69(7.7,-4.6) 70(7.7,-4.2) 71(7.7,-3.8) 72(7.7,-3.4) 73(7.7,-3) 74(7.7,-2.6) 75(7.7,-2.2) 76(7.7,-1.8) 77(7.7,-1.4) 78(7.7,-1) 79(7.7,-0.6) 80(7.7,-0.2) 81(7.7,0.2) 82(7.7,0.6) 83(7.7,1) 84(7.7,1.4) 85(7.7,1.8) 86(7.7,2.2) 87(7.7,2.6) 88(7.7,3) 89(7.7,3.4) 90(7.7,3.8) 91(7.7,4.2) 92(7.7,4.6) 93(7.7,5) 94(7.7,5.4) 95(7.7,5.8) 96(7.7,6.2)
  oval 0.2x1.4 smd: 33(-6.2,-7.7) 34(-5.8,-7.7) 35(-5.4,-7.7) 36(-5,-7.7) 37(-4.6,-7.7) 38(-4.2,-7.7) 39(-3.8,-7.7) 40(-3.4,-7.7) 41(-3,-7.7) 42(-2.6,-7.7) 43(-2.2,-7.7) 44(-1.8,-7.7) 45(-1.4,-7.7) 46(-1,-7.7) 47(-0.6,-7.7) 48(-0.2,-7.7) 49(0.2,-7.7) 50(0.6,-7.7) 51(1,-7.7) 52(1.4,-7.7) 53(1.8,-7.7) 54(2.2,-7.7) 55(2.6,-7.7) 56(3,-7.7) 57(3.4,-7.7) 58(3.8,-7.7) 59(4.2,-7.7) 60(4.6,-7.7) 61(5,-7.7) 62(5.4,-7.7) 63(5.8,-7.7) 64(6.2,-7.7) 97(6.2,7.7) 98(5.8,7.7) 99(5.4,7.7) 100(5,7.7) 101(4.6,7.7) 102(4.2,7.7) 103(3.8,7.7) 104(3.4,7.7) 105(3,7.7) 106(2.6,7.7) 107(2.2,7.7) 108(1.8,7.7) 109(1.4,7.7) 110(1,7.7) 111(0.6,7.7) 112(0.2,7.7) 113(-0.2,7.7) 114(-0.6,7.7) 115(-1,7.7) 116(-1.4,7.7) 117(-1.8,7.7) 118(-2.2,7.7) 119(-2.6,7.7) 120(-3,7.7) 121(-3.4,7.7) 122(-3.8,7.7) 123(-4.2,7.7) 124(-4.6,7.7) 125(-5,7.7) 126(-5.4,7.7) 127(-5.8,7.7) 128(-6.2,7.7)
  silkscreen extent -7.7,-6.3 6.3,7, body extent -8,-8 8,8, height 1.07
RER0016A-MFG [mm] "Recommended Land Pattern"
  rrect36% 0.3x0.275 smd paste-1000 mask+0: 1(-1.25,0.75) 2(-1.25,0.25) 3(-1.25,-0.25) 4(-1.25,-0.75) 9(1.25,-0.75) 10(1.25,-0.25) 11(1.25,0.25) 12(1.25,0.75)
  rrect36% 0.275x0.3 smd paste-1000 mask+0: 5(-0.75,-1.25) 6(-0.25,-1.25) 7(0.25,-1.25) 8(0.75,-1.25) 13(0.75,1.25) 14(0.25,1.25) 15(-0.25,1.25) 16(-0.75,1.25)
  rrect10% 1x1 smd paste-1000 mask+0: 17(0,0)
  silkscreen extent -1.65,-1.55 1.55,1.65, body extent -1.5,-1.5 1.5,1.5, height 1.5
RGE0024H-MFG [mm]
  rrect42% 0.58x0.24 smd paste+0 mask+0: 1(-1.913,1.25) 2(-1.913,0.75) 3(-1.913,0.25) 4(-1.913,-0.25) 5(-1.913,-0.75) 6(-1.913,-1.25) 13(1.913,-1.25) 14(1.913,-0.75) 15(1.913,-0.25) 16(1.913,0.25) 17(1.913,0.75) 18(1.913,1.25)
  rrect42% 0.24x0.58 smd paste+0 mask+0: 7(-1.25,-1.913) 8(-0.75,-1.913) 9(-0.25,-1.913) 10(0.25,-1.913) 11(0.75,-1.913) 12(1.25,-1.913) 19(1.25,1.913) 20(0.75,1.913) 21(0.25,1.913) 22(-0.25,1.913) 23(-0.75,1.913) 24(-1.25,1.913)
  rrect4% 2.7x2.7 smd paste-1000 mask+0: 25(0,0)
  silkscreen extent -2.88,-2.05 2.05,2.05, body extent -2,-2 2,2, height 1
RHA0040M-MFG [mm]
  rrect40% 0.6x0.25 smd paste+0 mask+0: 1(-2.9,2.25) 2(-2.9,1.75) 3(-2.9,1.25) 4(-2.9,0.75) 5(-2.9,0.25) 6(-2.9,-0.25) 7(-2.9,-0.75) 8(-2.9,-1.25) 9(-2.9,-1.75) 10(-2.9,-2.25) 21(2.9,-2.25) 22(2.9,-1.75) 23(2.9,-1.25) 24(2.9,-0.75) 25(2.9,-0.25) 26(2.9,0.25) 27(2.9,0.75) 28(2.9,1.25) 29(2.9,1.75) 30(2.9,2.25)
  rrect40% 0.25x0.6 smd paste+0 mask+0: 11(-2.25,-2.9) 12(-1.75,-2.9) 13(-1.25,-2.9) 14(-0.75,-2.9) 15(-0.25,-2.9) 16(0.25,-2.9) 17(0.75,-2.9) 18(1.25,-2.9) 19(1.75,-2.9) 20(2.25,-2.9) 31(2.25,2.9) 32(1.75,2.9) 33(1.25,2.9) 34(0.75,2.9) 35(0.25,2.9) 36(-0.25,2.9) 37(-0.75,2.9) 38(-1.25,2.9) 39(-1.75,2.9) 40(-2.25,2.9)
  rrect2% 4.15x4.15 smd paste-1000 mask+0: 41(0,0)
  silkscreen extent -3.9,-3.05 3.05,3.05, body extent -3,-3 3,3, height 1.02
RHB0032M-MFG [mm] "Recommended Land Pattern"
  rrect40% 0.6x0.25 smd paste+0 mask+0: 1(-2.4,1.75) 2(-2.4,1.25) 3(-2.4,0.75) 4(-2.4,0.25) 5(-2.4,-0.25) 6(-2.4,-0.75) 7(-2.4,-1.25) 8(-2.4,-1.75) 17(2.4,-1.75) 18(2.4,-1.25) 19(2.4,-0.75) 20(2.4,-0.25) 21(2.4,0.25) 22(2.4,0.75) 23(2.4,1.25) 24(2.4,1.75)
  rrect40% 0.25x0.6 smd paste+0 mask+0: 9(-1.75,-2.4) 10(-1.25,-2.4) 11(-0.75,-2.4) 12(-0.25,-2.4) 13(0.25,-2.4) 14(0.75,-2.4) 15(1.25,-2.4) 16(1.75,-2.4) 25(1.75,2.4) 26(1.25,2.4) 27(0.75,2.4) 28(0.25,2.4) 29(-0.25,2.4) 30(-0.75,2.4) 31(-1.25,2.4) 32(-1.75,2.4)
  rrect5% 2.1x2.1 smd paste-1000 mask+0: 33(0,0)
  silkscreen extent -3.37,-2.55 2.55,2.55, body extent -2.5,-2.5 2.5,2.5, height 1
Samtec_FTR-110-51-x-D-06 [mm] "Header, 1.27mm, 10x2, SMT"
  rect 2.87x0.711 smd: 1(-2.705,5.715) 2(2.705,5.715) 3(-2.705,4.445) 4(2.705,4.445) 5(-2.705,3.175) 6(2.705,3.175) 7(-2.705,1.905) 8(2.705,1.905) 9(-2.705,0.635) 10(2.705,0.635) 11(-2.705,-0.635) 12(2.705,-0.635) 13(-2.705,-1.905) 14(2.705,-1.905) 15(-2.705,-3.175) 16(2.705,-3.175) 17(-2.705,-4.445) 18(2.705,-4.445) 19(-2.705,-5.715) 20(2.705,-5.715)
  silkscreen extent -2.49,-6.35 2.49,6.7, body extent -3.76,-6.35 3.76,6.35, height 8.64
SMC_Bi [mil] "SMC, no polarity mark"
  rect 110x150 smd: 1(-140.49,0) 2(140.49,0)
  body extent -156,-116 156,116, height 92
SOT-323 [mm] "Diodes Inc recommended land pattern.  2016-02-24"
  rrect21% 0.6x0.47 smd: 1(-0.95,0.65) 2(-0.95,-0.65) 3(0.95,0)
  silkscreen extent -1.14,-1.22 0.77,1.22, body extent -1.13,-1.13 1.12,1.12, height 1.13
SW_434153017835 [mm] "SMD, 4-Leads, Body 3.5x2.9mm"
  rect 1.15x1.05 smd: 1(-1.675,0.725) 2(-1.675,-0.725) 3(1.675,0.725) 4(1.675,-0.725)
  silkscreen extent -0.7,-1.4 0.7,1.6, body extent -2.15,-1.45 2.15,1.45, height 1.7
TI_Stacked_Overlay_Small [mil]
  silkscreen extent -418,-98 418,98
TP_25MIL-SMT [mil]
  round 25 smd mask-2.5: 1(0,0)
TP_50MIL-25MILHOLE [mil]
  round 50 hole 25: 1(0,0)
TP_SM_1MM [mm] "1mm Test Point, SMT"
  round 1 smd paste-0.5: 1(0,0)
TSSOP-8 [mm] "TSSOP, 8-Leads, Body 3.1x4.5mm (max), Pitch 0.65mm, IPC Medium Density"
  rrect50% 1.7x0.35 smd: 1(-2.85,0.975) 2(-2.85,0.325) 3(-2.85,-0.325) 4(-2.85,-0.975) 5(2.85,-0.975) 6(2.85,-0.325) 7(2.85,0.325) 8(2.85,0.975)
  silkscreen extent -2.98,-1.55 1.6,1.82, body extent -3.2,-1.55 3.2,1.55, height 1.07
WCAP-AS5H_D10H10.5 [mm] "Aluminum Electrolytic Capacitors, 10x10.5mm"
  rect 4.4x1.9 smd: 1(4.35,0) 2(-4.35,0)
  silkscreen extent -5.25,-5.25 5.25,5.25, body extent -5.5,-5.15 5.5,5.15, height 10.5
WCAP-CSGP_0201_L0.6W0.3H0.3 [mm] "Ceramic Capacitors, body 0.60x0.30mm"
  rect 0.21x0.3 smd: 1(-0.22,0) 2(0.22,0)
  body extent -0.3,-0.15 0.3,0.15, height 0.3
WCAP-CSGP_0402_L1W0.5H0.5 [mm] "Ceramic Capacitors, body 1x0.5mm"
  rect 0.5x0.5 smd: 1(-0.5,0) 2(0.5,0)
  body extent -0.5,-0.25 0.5,0.25, height 0.5
WCAP-CSGP_0603_L1.6W0.8H0.8_Reflow [mm] "Ceramic Capacitors, body 1.6x0.8mm"
  rect 0.8x0.8 smd: 1(-0.75,0) 2(0.75,0)
  body extent -0.8,-0.4 0.8,0.4, height 0.8
WCAP-CSGP_0805_L2W1.25H0.8_Reflow [mm] "Ceramic Capacitors, body 2x1.25mm"
  rect 0.9x1.3 smd: 1(-0.95,0) 2(0.95,0)
  body extent -1,-0.62 1,0.63, height 0.8
WCAP-CSGP_1206_L3.2W1.6H0.8 [mm] "Ceramic Capacitors, body 3.2x1.6mm"
  rect 0.9x1.6 smd: 1(-1.55,0) 2(1.55,0)
  silkscreen extent -0.8,-0.87 0.8,0.87, body extent -1.6,-0.8 1.6,0.8, height 0.8
WCAP-CSGP_1206_L3.2W1.6H1.6 [mm] "Ceramic Capacitors, body 3.2x1.6mm"
  rect 0.9x1.6 smd: 1(-1.55,0) 2(1.55,0)
  silkscreen extent -0.8,-0.95 0.8,0.95, body extent -1.6,-0.8 1.6,0.8, height 1.6
WCAP-CSGP_1210_L3.2W2.5H2.5 [mm] "Ceramic Capacitors, body 3.2x2.5mm"
  rect 0.9x2.5 smd: 1(-1.55,0) 2(1.55,0)
  silkscreen extent -0.8,-1.4 0.8,1.4, body extent -1.6,-1.25 1.6,1.25, height 2.5
WCAP-CSRF_0402_L1W0.5H0.5 [mm] "Radio Frequency MLCC, body 1x0.5mm"
  rect 0.5x0.5 smd: 1(-0.5,0) 2(0.5,0)
  body extent -0.5,-0.25 0.5,0.25, height 0.5
WE-MAPI_3020 [mm] "SMT Shielded Power Inductor, body 3x3mm"
  rect 1.3x3.4 smd: 1(-1.05,0) 2(1.05,0)
  Top Layer keep-out region: -0.3,1.7 0.3,1.7 0.3,-1.7 -0.3,-1.7
  body extent -1.5,-1.5 1.5,1.5, height 2
WE-MAPI_5030 [mm] "SMD Power Inductor, 2-leads, body 5.6x5.6mm"
  rect 1.7x5.6 smd: 1(-1.95,0) 2(1.95,0)
  silkscreen extent -0.75,-2.8 0.75,2.8, body extent -2.7,-2.7 2.7,2.7, height 3.1
WE-VS_0603 [mm] "SMD Varistor, 2-Leads, body 1.60x0.80mm"
  rect 0.75x0.7 smd: 1(-0.725,0) 2(0.725,0)
  body extent -0.8,-0.4 0.8,0.4, height 0.8
WEEE_Minimum [mil] "WEEElie bin"
  silkscreen extent -95,-172 99,104
WL-SMCC_0402_Green [mm] "SMD, 2-Leads, Body 1x0.5mm"
  rrect17% 0.6x0.6 smd: 1(-0.55,0) 2(0.55,0)
  body extent -0.5,-0.25 0.5,0.25, height 0.39
WURTH_61300311121 [mm] "Header, 2.54mm, 3x1, TH"
  rrect50% 1.65x1.65 hole 1.15: 1(-2.54,0)
  round 1.65 hole 1.15: 2(0,0) 3(2.54,0)
  body extent -3.81,-1.27 3.81,1.27, height 8.54
WURTH_61300411121 [mm] "Header, 2.54mm, 4x1, TH"
  rrect50% 1.65x1.65 hole 1.15: 1(-3.81,0)
  round 1.65 hole 1.15: 2(-1.27,0) 3(1.27,0) 4(3.81,0)
  body extent -5.08,-1.27 5.08,1.27, height 8.54
ZFG0304A-MFG [mm] "Recommended Land Pattern"
  round 0.35 smd paste+0 mask-1000: A1(-6.175,6.175) A2(-5.525,6.175) A3(-4.875,6.175) A4(-4.225,6.175) A5(-3.575,6.175) A6(-2.925,6.175) A7(-2.275,6.175) A8(-1.625,6.175) A9(-0.975,6.175) A10(-0.325,6.175) A11(0.325,6.175) A12(0.975,6.175) A13(1.625,6.175) A14(2.275,6.175) A15(2.925,6.175) A16(3.575,6.175) A17(4.225,6.175) A18(4.875,6.175) A19(5.525,6.175) A20(6.175,6.175) B1(-6.175,5.525) B2(-5.525,5.525) B3(-4.875,5.525) B4(-4.225,5.525) B5(-3.575,5.525) B6(-2.925,5.525) B7(-2.275,5.525) B8(-1.625,5.525) B9(-0.975,5.525) B10(-0.325,5.525) B11(0.325,5.525) B12(0.975,5.525) B13(1.625,5.525) B14(2.275,5.525) B15(2.925,5.525) B16(3.575,5.525) B17(4.225,5.525) B18(4.875,5.525) B19(5.525,5.525) B20(6.175,5.525) C1(-6.175,4.875) C2(-5.525,4.875) C3(-4.875,4.875) C5(-3.575,4.875) C7(-2.275,4.875) C9(-0.975,4.875) C12(0.975,4.875) C14(2.275,4.875) C16(3.575,4.875) C18(4.875,4.875) C19(5.525,4.875) C20(6.175,4.875) D1(-6.175,4.225) D2(-5.525,4.225) D4(-4.225,4.225) D6(-2.925,4.225) D8(-1.625,4.225) D10(-0.325,4.225) D11(0.325,4.225) D13(1.625,4.225) D15(2.925,4.225) D17(4.225,4.225) D19(5.525,4.225) D20(6.175,4.225) E1(-6.175,3.575) E2(-5.525,3.575) E3(-4.875,3.575) E5(-3.575,3.575) E7(-2.275,3.575) E9(-0.975,3.575) E12(0.975,3.575) E14(2.275,3.575) E16(3.575,3.575) E18(4.875,3.575) E19(5.525,3.575) E20(6.175,3.575) F1(-6.175,2.925) F2(-5.525,2.925) F4(-4.225,2.925) F6(-2.925,2.925) F7(-2.275,2.925) F9(-0.975,2.925) F12(0.975,2.925) F14(2.275,2.925) F15(2.925,2.925) F17(4.225,2.925) F19(5.525,2.925) F20(6.175,2.925) G1(-6.175,2.275) G2(-5.525,2.275) G3(-4.875,2.275) G5(-3.575,2.275) G6(-2.925,2.275) G7(-2.275,2.275) G8(-1.625,2.275) G9(-0.975,2.275) G10(-0.325,2.275) G11(0.325,2.275) G12(0.975,2.275) G13(1.625,2.275) G14(2.275,2.275) G15(2.925,2.275) G16(3.575,2.275) G18(4.875,2.275) G19(5.525,2.275) G20(6.175,2.275) H1(-6.175,1.625) H2(-5.525,1.625) H4(-4.225,1.625) H7(-2.275,1.625) H8(-1.625,1.625) H9(-0.975,1.625) H10(-0.325,1.625) H11(0.325,1.625) H12(0.975,1.625) H13(1.625,1.625) H14(2.275,1.625) H17(4.225,1.625) H19(5.525,1.625) H20(6.175,1.625) J1(-6.175,0.975) J2(-5.525,0.975) J3(-4.875,0.975) J5(-3.575,0.975) J6(-2.925,0.975) J7(-2.275,0.975) J8(-1.625,0.975) J9(-0.975,0.975) J10(-0.325,0.975) J11(0.325,0.975) J12(0.975,0.975) J13(1.625,0.975) J14(2.275,0.975) J15(2.925,0.975) J16(3.575,0.975) J18(4.875,0.975) J19(5.525,0.975) J20(6.175,0.975) K1(-6.175,0.325) K2(-5.525,0.325) K4(-4.225,0.325) K7(-2.275,0.325) K8(-1.625,0.325) K9(-0.975,0.325) K10(-0.325,0.325) K11(0.325,0.325) K12(0.975,0.325) K13(1.625,0.325) K14(2.275,0.325) K17(4.225,0.325) K19(5.525,0.325) K20(6.175,0.325) L1(-6.175,-0.325) L2(-5.525,-0.325) L4(-4.225,-0.325) L7(-2.275,-0.325) L8(-1.625,-0.325) L9(-0.975,-0.325) L10(-0.325,-0.325) L11(0.325,-0.325) L12(0.975,-0.325) L13(1.625,-0.325) L14(2.275,-0.325) L17(4.225,-0.325) L19(5.525,-0.325) L20(6.175,-0.325) M1(-6.175,-0.975) M2(-5.525,-0.975) M3(-4.875,-0.975) M5(-3.575,-0.975) M6(-2.925,-0.975) M7(-2.275,-0.975) M8(-1.625,-0.975) M9(-0.975,-0.975) M10(-0.325,-0.975) M11(0.325,-0.975) M12(0.975,-0.975) M13(1.625,-0.975) M14(2.275,-0.975) M15(2.925,-0.975) M16(3.575,-0.975) M18(4.875,-0.975) M19(5.525,-0.975) M20(6.175,-0.975) N1(-6.175,-1.625) N2(-5.525,-1.625) N4(-4.225,-1.625) N7(-2.275,-1.625) N8(-1.625,-1.625) N9(-0.975,-1.625) N10(-0.325,-1.625) N11(0.325,-1.625) N12(0.975,-1.625) N13(1.625,-1.625) N14(2.275,-1.625) N17(4.225,-1.625) N19(5.525,-1.625) N20(6.175,-1.625) P1(-6.175,-2.275) P2(-5.525,-2.275) P3(-4.875,-2.275) P5(-3.575,-2.275) P6(-2.925,-2.275) P7(-2.275,-2.275) P8(-1.625,-2.275) P9(-0.975,-2.275) P10(-0.325,-2.275) P11(0.325,-2.275) P12(0.975,-2.275) P13(1.625,-2.275) P14(2.275,-2.275) P15(2.925,-2.275) P16(3.575,-2.275) P18(4.875,-2.275) P19(5.525,-2.275) P20(6.175,-2.275) R1(-6.175,-2.925) R2(-5.525,-2.925) R4(-4.225,-2.925) R6(-2.925,-2.925) R7(-2.275,-2.925) R9(-0.975,-2.925) R12(0.975,-2.925) R14(2.275,-2.925) R15(2.925,-2.925) R17(4.225,-2.925) R19(5.525,-2.925) R20(6.175,-2.925) T1(-6.175,-3.575) T2(-5.525,-3.575) T3(-4.875,-3.575) T5(-3.575,-3.575) T7(-2.275,-3.575) T9(-0.975,-3.575) T12(0.975,-3.575) T14(2.275,-3.575) T16(3.575,-3.575) T18(4.875,-3.575) T19(5.525,-3.575) T20(6.175,-3.575) U1(-6.175,-4.225) U2(-5.525,-4.225) U4(-4.225,-4.225) U6(-2.925,-4.225) U8(-1.625,-4.225) U10(-0.325,-4.225) U11(0.325,-4.225) U13(1.625,-4.225) U15(2.925,-4.225) U17(4.225,-4.225) U19(5.525,-4.225) U20(6.175,-4.225) V1(-6.175,-4.875) V2(-5.525,-4.875) V3(-4.875,-4.875) V5(-3.575,-4.875) V7(-2.275,-4.875) V9(-0.975,-4.875) V12(0.975,-4.875) V14(2.275,-4.875) V16(3.575,-4.875) V18(4.875,-4.875) V19(5.525,-4.875) V20(6.175,-4.875) W1(-6.175,-5.525) W2(-5.525,-5.525) W3(-4.875,-5.525) W4(-4.225,-5.525) W5(-3.575,-5.525) W6(-2.925,-5.525) W7(-2.275,-5.525) W8(-1.625,-5.525) W9(-0.975,-5.525) W10(-0.325,-5.525) W11(0.325,-5.525) W12(0.975,-5.525) W13(1.625,-5.525) W14(2.275,-5.525) W15(2.925,-5.525) W16(3.575,-5.525) W17(4.225,-5.525) W18(4.875,-5.525) W19(5.525,-5.525) W20(6.175,-5.525) Y1(-6.175,-6.175) Y2(-5.525,-6.175) Y3(-4.875,-6.175) Y4(-4.225,-6.175) Y5(-3.575,-6.175) Y6(-2.925,-6.175) Y7(-2.275,-6.175) Y8(-1.625,-6.175) Y9(-0.975,-6.175) Y10(-0.325,-6.175) Y11(0.325,-6.175) Y12(0.975,-6.175) Y13(1.625,-6.175) Y14(2.275,-6.175) Y15(2.925,-6.175) Y16(3.575,-6.175) Y17(4.225,-6.175) Y18(4.875,-6.175) Y19(5.525,-6.175) Y20(6.175,-6.175)
  silkscreen extent -7.38,-6.78 6.78,6.77, body extent -6.63,-6.63 6.63,6.63, height 1.3

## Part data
C1.1 C1.2 C1.3 C1.4 C1.5 C1.6 C1.7 C1.8: library part CMP-0119636-1, "WCAP-CSGP Multilayer Ceramic Chip Capacitor, General Purpose, size 1206, X7R, 1µF, 50VDC", Capacitance Tolerance=+/-10%, Case/Size Code=1206, Insulation Resistance=0.5GOhm, Manufacturer="Wurth Elektronik", Operating Temperature Max=125°C, Operating Temperature Min=-55°C, PartNumber='885012208093, Rated Voltage (DC)=50V
C2.1 C2.2 C2.3 C2.4 C2.5 C2.6 C2.7 C2.8: library part CMP-0115435-1, "WCAP-CSGP Multilayer Ceramic Chip Capacitor, General Purpose, size 0603, X7R, 1µF, 16VDC", Capacitance Tolerance=+/-10%, Case/Size Code=0603, Insulation Resistance=0.1GOhm, Manufacturer="Wurth Elektronik", Operating Temperature Max=125°C, Operating Temperature Min=-55°C, Rated Voltage (DC)=16V
C3 C4 C5 C6 C7 C8 C9 C10 C23 C24 C30 C33 C34 C36 C37 C38 C103 C117 C135.1 C135.2 C137.1 C137.2 C139.1 C139.2 C141.1 C141.2 C142.1 C142.2 C143 C149 C150 C151 C152 C153 C157 C162: library part CMP-0119143-1, "WCAP-CSGP Multilayer Ceramic Chip Capacitor, General Purpose, size 0402, X5R, 100nF, 25VDC", Capacitance Tolerance=+/-20%, Case/Size Code=0402, Insulation Resistance=5GOhm, Manufacturer="Wurth Elektronik", Operating Temperature Max=85°C, Operating Temperature Min=-55°C, PartNumber='885012105018, Rated Voltage (DC)=25V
